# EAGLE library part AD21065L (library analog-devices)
ANALOG DEVICES
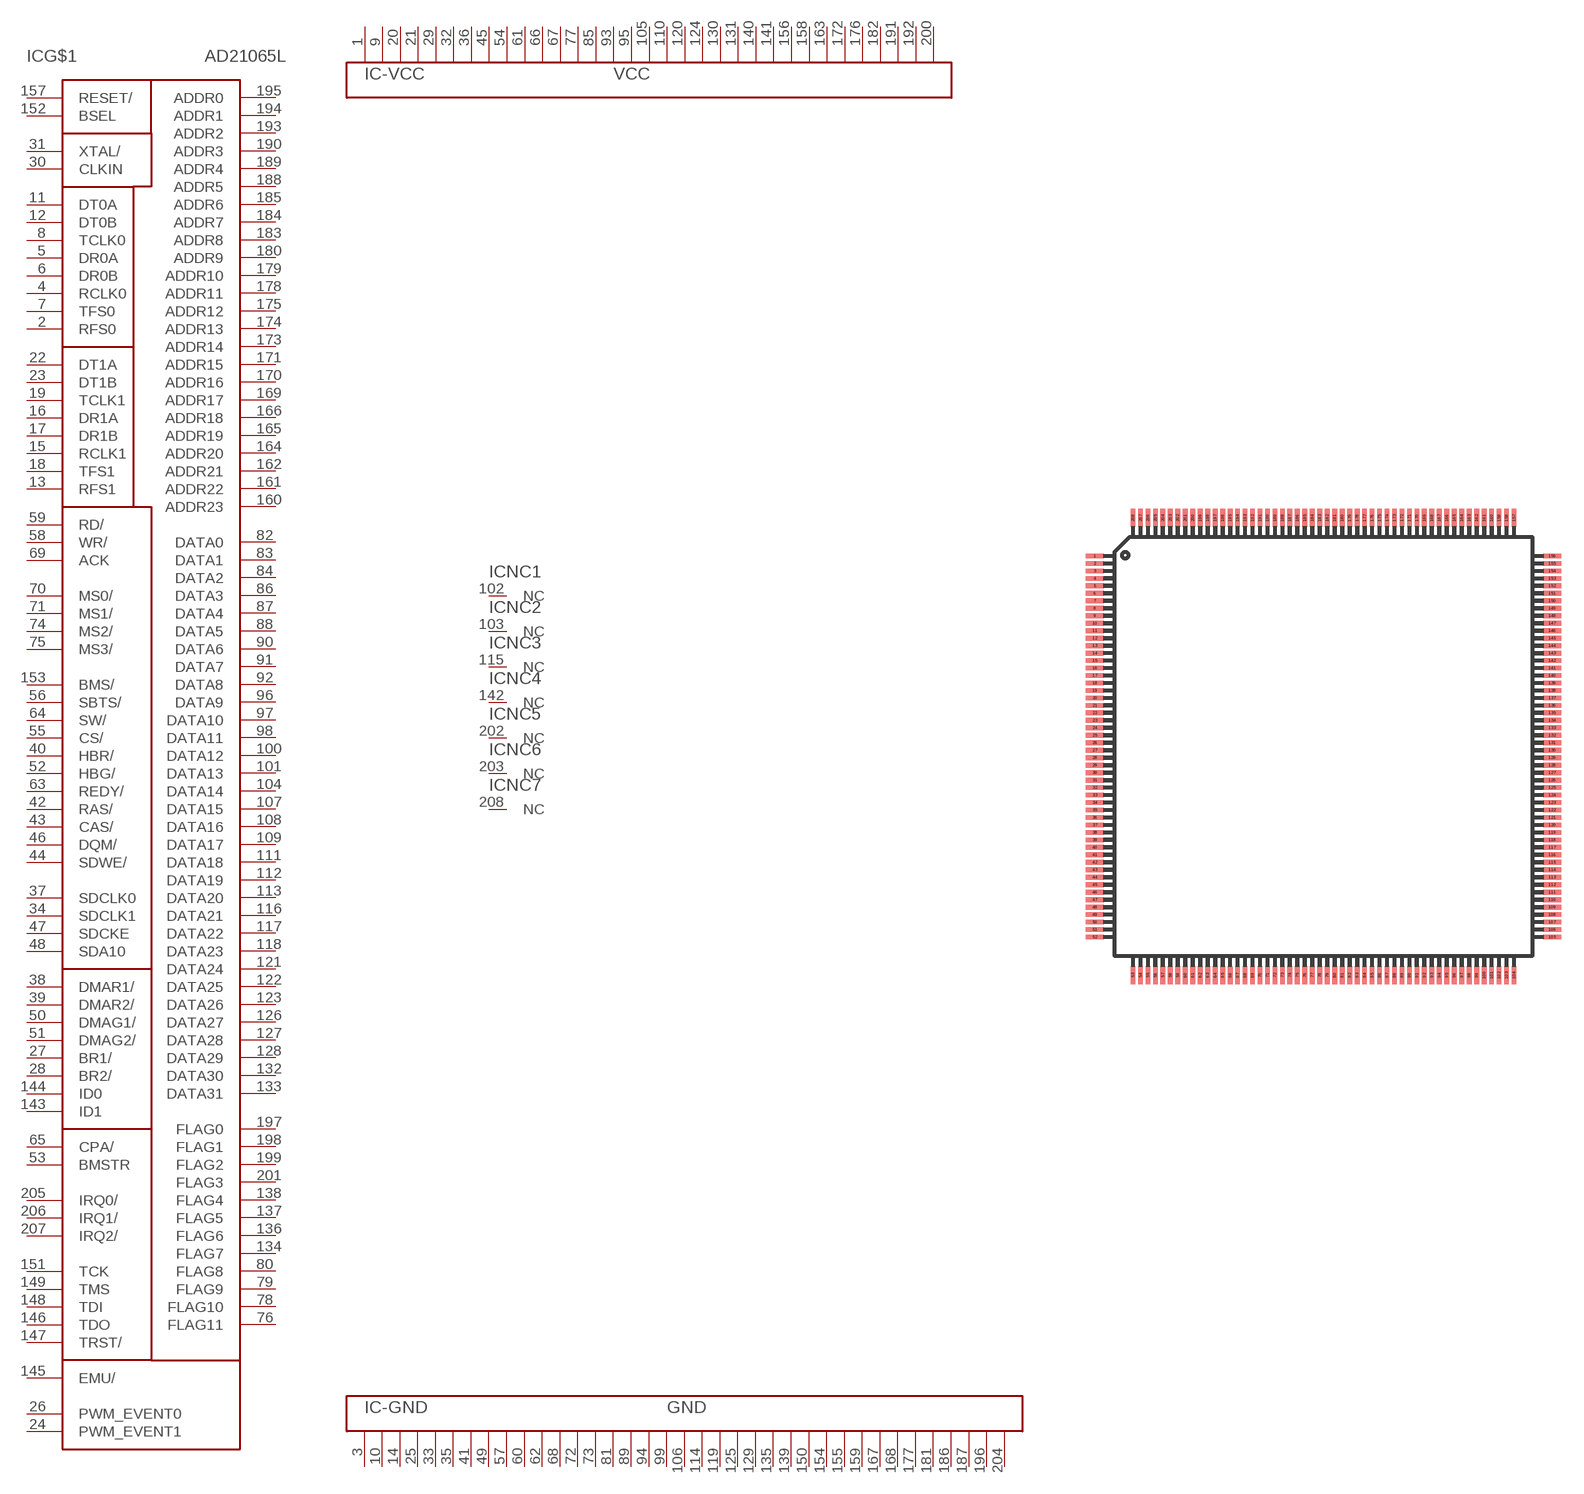
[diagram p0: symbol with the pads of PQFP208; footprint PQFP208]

Designator prefix IC; gates G$1=SP21065L -GND=GND37 NC1=NC NC2=NC NC3=NC NC4=NC NC5=NC NC6=NC NC7=NC -VCC=VCC32

## AD21065L (OC_FARNELL: unknown; OC_NEWARK: unknown)  [PQFP208]
1  -VCC:VCC  pwr
2  G$1:RFS0
3  -GND:GND  pwr
4  G$1:RCLK0
5  G$1:DR0A  in
6  G$1:DR0B  in
7  G$1:TFS0
8  G$1:TCLK0
9  -VCC:VCC  pwr
10  -GND:GND  pwr
11  G$1:DT0A  out
12  G$1:DT0B  out
13  G$1:RFS1
14  -GND:GND  pwr
15  G$1:RCLK1
16  G$1:DR1A  in
17  G$1:DR1B  in
18  G$1:TFS1
19  G$1:TCLK1
20  -VCC:VCC  pwr
21  -VCC:VCC  pwr
22  G$1:DT1A  out
23  G$1:DT1B  out
24  G$1:PWM_EVENT1
25  -GND:GND  pwr
26  G$1:PWM_EVENT0
27  G$1:BR1/
28  G$1:BR2/
29  -VCC:VCC  pwr
30  G$1:CLKIN  in
31  G$1:XTAL/  out
32  -VCC:VCC  pwr
33  -GND:GND  pwr
34  G$1:SDCLK1  hiz
35  -GND:GND  pwr
36  -VCC:VCC  pwr
37  G$1:SDCLK0  hiz
38  G$1:DMAR1/  in
39  G$1:DMAR2/  in
40  G$1:HBR/  in
41  -GND:GND  pwr
42  G$1:RAS/  hiz
43  G$1:CAS/  hiz
44  G$1:SDWE/  hiz
45  -VCC:VCC  pwr
46  G$1:DQM/  hiz
47  G$1:SDCKE  hiz
48  G$1:SDA10  hiz
49  -GND:GND  pwr
50  G$1:DMAG1/  hiz
51  G$1:DMAG2/  hiz
52  G$1:HBG/
53  G$1:BMSTR  out
54  -VCC:VCC  pwr
55  G$1:CS/  in
56  G$1:SBTS/  in
57  -GND:GND  pwr
58  G$1:WR/  hiz
59  G$1:RD/  hiz
60  -GND:GND  pwr
61  -VCC:VCC  pwr
62  -GND:GND  pwr
63  G$1:REDY/  out
64  G$1:SW/  hiz
65  G$1:CPA/
66  -VCC:VCC  pwr
67  -VCC:VCC  pwr
68  -GND:GND  pwr
69  G$1:ACK
70  G$1:MS0/  hiz
71  G$1:MS1/  hiz
72  -GND:GND  pwr
73  -GND:GND  pwr
74  G$1:MS2/  hiz
75  G$1:MS3/  hiz
76  G$1:FLAG11
77  -VCC:VCC  pwr
78  G$1:FLAG10
79  G$1:FLAG9
80  G$1:FLAG8
81  -GND:GND  pwr
82  G$1:DATA0
83  G$1:DATA1
84  G$1:DATA2
85  -VCC:VCC  pwr
86  G$1:DATA3
87  G$1:DATA4
88  G$1:DATA5
89  -GND:GND  pwr
90  G$1:DATA6
91  G$1:DATA7
92  G$1:DATA8
93  -VCC:VCC  pwr
94  -GND:GND  pwr
95  -VCC:VCC  pwr
96  G$1:DATA9
97  G$1:DATA10
98  G$1:DATA11
99  -GND:GND  pwr
100  G$1:DATA12
101  G$1:DATA13
102  NC1:NC  nc
103  NC2:NC  nc
104  G$1:DATA14
105  -VCC:VCC  pwr
106  -GND:GND  pwr
107  G$1:DATA15
108  G$1:DATA16
109  G$1:DATA17
110  -VCC:VCC  pwr
111  G$1:DATA18
112  G$1:DATA19
113  G$1:DATA20
114  -GND:GND  pwr
115  NC3:NC  nc
116  G$1:DATA21
117  G$1:DATA22
118  G$1:DATA23
119  -GND:GND  pwr
120  -VCC:VCC  pwr
121  G$1:DATA24
122  G$1:DATA25
123  G$1:DATA26
124  -VCC:VCC  pwr
125  -GND:GND  pwr
126  G$1:DATA27
127  G$1:DATA28
128  G$1:DATA29
129  -GND:GND  pwr
130  -VCC:VCC  pwr
131  -VCC:VCC  pwr
132  G$1:DATA30
133  G$1:DATA31
134  G$1:FLAG7
135  -GND:GND  pwr
136  G$1:FLAG6
137  G$1:FLAG5
138  G$1:FLAG4
139  -GND:GND  pwr
140  -VCC:VCC  pwr
141  -VCC:VCC  pwr
142  NC4:NC  nc
143  G$1:ID1  in
144  G$1:ID0  in
145  G$1:EMU/  out
146  G$1:TDO  out
147  G$1:TRST/  in
148  G$1:TDI  in
149  G$1:TMS  in
150  -GND:GND  pwr
151  G$1:TCK  in
152  G$1:BSEL  in
153  G$1:BMS/
154  -GND:GND  pwr
155  -GND:GND  pwr
156  -VCC:VCC  pwr
157  G$1:RESET/  in
158  -VCC:VCC  pwr
159  -GND:GND  pwr
160  G$1:ADDR23
161  G$1:ADDR22
162  G$1:ADDR21
163  -VCC:VCC  pwr
164  G$1:ADDR20
165  G$1:ADDR19
166  G$1:ADDR18
167  -GND:GND  pwr
168  -GND:GND  pwr
169  G$1:ADDR17
170  G$1:ADDR16
171  G$1:ADDR15
172  -VCC:VCC  pwr
173  G$1:ADDR14
174  G$1:ADDR13
175  G$1:ADDR12
176  -VCC:VCC  pwr
177  -GND:GND  pwr
178  G$1:ADDR11
179  G$1:ADDR10
180  G$1:ADDR9
181  -GND:GND  pwr
182  -VCC:VCC  pwr
183  G$1:ADDR8
184  G$1:ADDR7
185  G$1:ADDR6
186  -GND:GND  pwr
187  -GND:GND  pwr
188  G$1:ADDR5
189  G$1:ADDR4
190  G$1:ADDR3
191  -VCC:VCC  pwr
192  -VCC:VCC  pwr
193  G$1:ADDR2
194  G$1:ADDR1
195  G$1:ADDR0
196  -GND:GND  pwr
197  G$1:FLAG0
198  G$1:FLAG1
199  G$1:FLAG2
200  -VCC:VCC  pwr
201  G$1:FLAG3
202  NC5:NC  nc
203  NC6:NC  nc
204  -GND:GND  pwr
205  G$1:IRQ0/  in
206  G$1:IRQ1/  in
207  G$1:IRQ2/  in
208  NC7:NC  nc

## Footprint PQFP208 (pad centres in mm)
PLASTIC QUAD FLAT PACK
smd 1.2 x 0.32: 1 -15.3,12.75; 2 -15.3,12.25; 3 -15.3,11.75; 4 -15.3,11.25; 5 -15.3,10.75; 6 -15.3,10.25; 7 -15.3,9.75; 8 -15.3,9.25; 9 -15.3,8.75; 10 -15.3,8.25; 11 -15.3,7.75; 12 -15.3,7.25; 13 -15.3,6.75; 14 -15.3,6.25; 15 -15.3,5.75; 16 -15.3,5.25; 17 -15.3,4.75; 18 -15.3,4.25; 19 -15.3,3.75; 20 -15.3,3.25; 21 -15.3,2.75; 22 -15.3,2.25; 23 -15.3,1.75; 24 -15.3,1.25; 25 -15.3,0.75; 26 -15.3,0.25; 27 -15.3,-0.25; 28 -15.3,-0.75; 29 -15.3,-1.25; 30 -15.3,-1.75; 31 -15.3,-2.25; 32 -15.3,-2.75; 33 -15.3,-3.25; 34 -15.3,-3.75; 35 -15.3,-4.25; 36 -15.3,-4.75; 37 -15.3,-5.25; 38 -15.3,-5.75; 39 -15.3,-6.25; 40 -15.3,-6.75; 41 -15.3,-7.25; 42 -15.3,-7.75; 43 -15.3,-8.25; 44 -15.3,-8.75; 45 -15.3,-9.25; 46 -15.3,-9.75; 47 -15.3,-10.25; 48 -15.3,-10.75; 49 -15.3,-11.25; 50 -15.3,-11.75; 51 -15.3,-12.25; 52 -15.3,-12.75; 105 15.3,-12.75; 106 15.3,-12.25; 107 15.3,-11.75; 108 15.3,-11.25; 109 15.3,-10.75; 110 15.3,-10.25; 111 15.3,-9.75; 112 15.3,-9.25; 113 15.3,-8.75; 114 15.3,-8.25; 115 15.3,-7.75; 116 15.3,-7.25; 117 15.3,-6.75; 118 15.3,-6.25; 119 15.3,-5.75; 120 15.3,-5.25; 121 15.3,-4.75; 122 15.3,-4.25; 123 15.3,-3.75; 124 15.3,-3.25; 125 15.3,-2.75; 126 15.3,-2.25; 127 15.3,-1.75; 128 15.3,-1.25; 129 15.3,-0.75; 130 15.3,-0.25; 131 15.3,0.25; 132 15.3,0.75; 133 15.3,1.25; 134 15.3,1.75; 135 15.3,2.25; 136 15.3,2.75; 137 15.3,3.25; 138 15.3,3.75; 139 15.3,4.25; 140 15.3,4.75; 141 15.3,5.25; 142 15.3,5.75; 143 15.3,6.25; 144 15.3,6.75; 145 15.3,7.25; 146 15.3,7.75; 147 15.3,8.25; 148 15.3,8.75; 149 15.3,9.25; 150 15.3,9.75; 151 15.3,10.25; 152 15.3,10.75; 153 15.3,11.25; 154 15.3,11.75; 155 15.3,12.25; 156 15.3,12.75
smd 0.32 x 1.2: 53 -12.75,-15.3; 54 -12.25,-15.3; 55 -11.75,-15.3; 56 -11.25,-15.3; 57 -10.75,-15.3; 58 -10.25,-15.3; 59 -9.75,-15.3; 60 -9.25,-15.3; 61 -8.75,-15.3; 62 -8.25,-15.3; 63 -7.75,-15.3; 64 -7.25,-15.3; 65 -6.75,-15.3; 66 -6.25,-15.3; 67 -5.75,-15.3; 68 -5.25,-15.3; 69 -4.75,-15.3; 70 -4.25,-15.3; 71 -3.75,-15.3; 72 -3.25,-15.3; 73 -2.75,-15.3; 74 -2.25,-15.3; 75 -1.75,-15.3; 76 -1.25,-15.3; 77 -0.75,-15.3; 78 -0.25,-15.3; 79 0.25,-15.3; 80 0.75,-15.3; 81 1.25,-15.3; 82 1.75,-15.3; 83 2.25,-15.3; 84 2.75,-15.3; 85 3.25,-15.3; 86 3.75,-15.3; 87 4.25,-15.3; 88 4.75,-15.3; 89 5.25,-15.3; 90 5.75,-15.3; 91 6.25,-15.3; 92 6.75,-15.3; 93 7.25,-15.3; 94 7.75,-15.3; 95 8.25,-15.3; 96 8.75,-15.3; 97 9.25,-15.3; 98 9.75,-15.3; 99 10.25,-15.3; 100 10.75,-15.3; 101 11.25,-15.3; 102 11.75,-15.3; 103 12.25,-15.3; 104 12.75,-15.3; 157 12.75,15.3; 158 12.25,15.3; 159 11.75,15.3; 160 11.25,15.3; 161 10.75,15.3; 162 10.25,15.3; 163 9.75,15.3; 164 9.25,15.3; 165 8.75,15.3; 166 8.25,15.3; 167 7.75,15.3; 168 7.25,15.3; 169 6.75,15.3; 170 6.25,15.3; 171 5.75,15.3; 172 5.25,15.3; 173 4.75,15.3; 174 4.25,15.3; 175 3.75,15.3; 176 3.25,15.3; 177 2.75,15.3; 178 2.25,15.3; 179 1.75,15.3; 180 1.25,15.3; 181 0.75,15.3; 182 0.25,15.3; 183 -0.25,15.3; 184 -0.75,15.3; 185 -1.25,15.3; 186 -1.75,15.3; 187 -2.25,15.3; 188 -2.75,15.3; 189 -3.25,15.3; 190 -3.75,15.3; 191 -4.25,15.3; 192 -4.75,15.3; 193 -5.25,15.3; 194 -5.75,15.3; 195 -6.25,15.3; 196 -6.75,15.3; 197 -7.25,15.3; 198 -7.75,15.3; 199 -8.25,15.3; 200 -8.75,15.3; 201 -9.25,15.3; 202 -9.75,15.3; 203 -10.25,15.3; 204 -10.75,15.3; 205 -11.25,15.3; 206 -11.75,15.3; 207 -12.25,15.3; 208 -12.75,15.3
